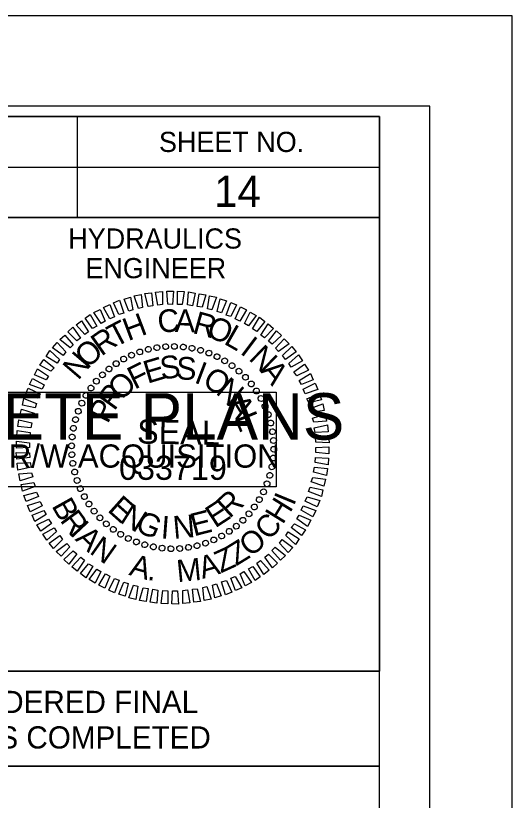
# Model space of a CAD drawing. Extents: x 1779926 to 1781626, y 618464 to 619564.
# Drawn here: x 1781502.7 to 1781626, y 619369.7 to 619564.2 of the extents above; entities that cross this region are included whole.
import ezdxf

# ---------------------------------------------------------------- set-up
doc = ezdxf.new("R2010")
doc.units = 0
for name, color, linetype in [('Old_Level_58', 7, 'Continuous'), ('Sheet Data Field CELL', 7, 'Continuous'), ('Sheet Plot Border Inside CELL', 7, 'Continuous'), ('Sheet Plot Border Outside CELL', 7, 'Continuous'), ('Sheet Professional Seal CELL', 7, 'Continuous'), ('Sheet Profile CELL', 7, 'Continuous'), ('Sheet Profile Grid Major CELL', 7, 'Continuous'), ('Sheet Profile Grid Minor CELL', 7, 'Continuous'), ('Sheet Sticker Exception Certification CELL', 7, 'Continuous'), ('Sheet Sticker Incomplete CELL', 7, 'Continuous')]:
    doc.layers.add(name, color=color, linetype=linetype)

msp = doc.modelspace()

# ---------------------------------------------------------------- linework, layer by layer
at = {"layer": 'Old_Level_58'}
msp.add_lwpolyline([(1781392.9, 619378.14), (1781592.95, 619378.14), (1781592.95, 619314.19), (1781392.9, 619314.19)], close=True, dxfattribs=at)
at = {"layer": 'Sheet Plot Border Inside CELL'}
msp.add_lwpolyline([(1779938.96, 618486.64), (1781605.46, 618486.64), (1781605.46, 619541.74), (1779938.96, 619541.74)], close=True, dxfattribs=at)
at = {"layer": 'Sheet Plot Border Outside CELL'}
msp.add_lwpolyline([(1779925.96, 618464.19), (1781625.96, 618464.19), (1781625.96, 619564.19), (1779925.96, 619564.19)], close=True, dxfattribs=at)
at = {"layer": 'Sheet Professional Seal CELL'}
for p, q in [((1781535.57, 619481.47), (1781535.57, 619481.47)), ((1781537.77, 619481.87), (1781537.77, 619481.87)), ((1781539.92, 619482.17), (1781539.92, 619482.17)), ((1781542.12, 619482.22), (1781542.12, 619482.22)), ((1781544.32, 619482.07), (1781544.32, 619482.07)), ((1781546.47, 619481.72), (1781546.47, 619481.72)), ((1781548.57, 619481.27), (1781548.57, 619481.27)), ((1781529.52, 619479.07), (1781529.52, 619479.07)), ((1781531.47, 619480.07), (1781531.47, 619480.07)), ((1781533.47, 619480.87), (1781533.47, 619480.87)), ((1781550.67, 619480.57), (1781550.67, 619480.57)), ((1781552.67, 619479.67), (1781552.67, 619479.67)), ((1781527.62, 619477.92), (1781527.62, 619477.92)), ((1781554.62, 619478.67), (1781554.62, 619478.67)), ((1781556.42, 619477.42), (1781556.42, 619477.42)), ((1781525.87, 619476.67), (1781525.87, 619476.67)), ((1781558.17, 619476.07), (1781558.17, 619476.07)), ((1781522.72, 619473.62), (1781522.72, 619473.62)), ((1781524.22, 619475.17), (1781524.22, 619475.17)), ((1781559.72, 619474.57), (1781559.72, 619474.57)), ((1781521.37, 619471.87), (1781521.37, 619471.87)), ((1781561.22, 619472.92), (1781561.22, 619472.92)), ((1781520.12, 619470.07), (1781520.12, 619470.07)), ((1781562.47, 619471.17), (1781562.47, 619471.17)), ((1781519.12, 619468.12), (1781519.12, 619468.12)), ((1781563.62, 619469.27), (1781563.62, 619469.27)), ((1781518.22, 619466.12), (1781518.22, 619466.12)), ((1781564.62, 619467.32), (1781564.62, 619467.32)), ((1781517.52, 619464.02), (1781517.52, 619464.02)), ((1781565.42, 619465.32), (1781565.42, 619465.32)), ((1781517.07, 619461.92), (1781517.07, 619461.92)), ((1781566.02, 619463.22), (1781566.02, 619463.22)), ((1781516.72, 619459.77), (1781516.72, 619459.77)), ((1781566.42, 619461.02), (1781566.42, 619461.02)), ((1781566.72, 619458.87), (1781566.72, 619458.87)), ((1781516.57, 619457.57), (1781516.57, 619457.57)), ((1781541.67, 619457.12), (1781541.67, 619457.12)), ((1781566.77, 619456.67), (1781566.77, 619456.67)), ((1781516.62, 619455.37), (1781516.62, 619455.37)), ((1781566.62, 619454.47), (1781566.62, 619454.47)), ((1781516.92, 619453.22), (1781516.92, 619453.22)), ((1781566.27, 619452.32), (1781566.27, 619452.32)), ((1781517.32, 619451.02), (1781517.32, 619451.02)), ((1781565.82, 619450.22), (1781565.82, 619450.22)), ((1781517.92, 619448.92), (1781517.92, 619448.92)), ((1781565.12, 619448.12), (1781565.12, 619448.12)), ((1781518.72, 619446.92), (1781518.72, 619446.92)), ((1781564.22, 619446.12), (1781564.22, 619446.12)), ((1781519.72, 619444.97), (1781519.72, 619444.97)), ((1781563.22, 619444.17), (1781563.22, 619444.17)), ((1781520.87, 619443.07), (1781520.87, 619443.07)), ((1781561.97, 619442.37), (1781561.97, 619442.37)), ((1781522.12, 619441.32), (1781522.12, 619441.32)), ((1781560.62, 619440.62), (1781560.62, 619440.62)), ((1781523.62, 619439.67), (1781523.62, 619439.67)), ((1781559.12, 619439.07), (1781559.12, 619439.07)), ((1781525.17, 619438.17), (1781525.17, 619438.17)), ((1781526.92, 619436.82), (1781526.92, 619436.82)), ((1781555.72, 619436.32), (1781555.72, 619436.32)), ((1781557.47, 619437.57), (1781557.47, 619437.57)), ((1781528.72, 619435.57), (1781528.72, 619435.57)), ((1781530.67, 619434.57), (1781530.67, 619434.57)), ((1781553.82, 619435.17), (1781553.82, 619435.17)), ((1781532.67, 619433.67), (1781532.67, 619433.67)), ((1781534.77, 619432.97), (1781534.77, 619432.97)), ((1781536.87, 619432.52), (1781536.87, 619432.52)), ((1781547.77, 619432.77), (1781547.77, 619432.77)), ((1781549.87, 619433.37), (1781549.87, 619433.37)), ((1781551.87, 619434.17), (1781551.87, 619434.17)), ((1781539.02, 619432.17), (1781539.02, 619432.17)), ((1781541.22, 619432.02), (1781541.22, 619432.02)), ((1781543.42, 619432.07), (1781543.42, 619432.07)), ((1781545.57, 619432.37), (1781545.57, 619432.37))]:
    msp.add_line(p, q, dxfattribs=at)
for points in [[(1781533.17, 619491.57), (1781532.12, 619494.72), (1781533.82, 619495.07), (1781534.22, 619491.82)], [(1781535.57, 619492.12), (1781534.77, 619495.32), (1781536.42, 619495.47), (1781536.77, 619492.27)], [(1781537.97, 619492.42), (1781537.42, 619495.62), (1781539.12, 619495.82), (1781539.17, 619492.57)], [(1781540.47, 619492.67), (1781540.22, 619495.92), (1781541.87, 619495.87), (1781541.67, 619492.62)], [(1781542.87, 619492.62), (1781542.87, 619495.87), (1781544.52, 619495.82), (1781544.07, 619492.57)], [(1781545.37, 619492.47), (1781545.57, 619495.72), (1781547.22, 619495.42), (1781546.57, 619492.27)], [(1781547.77, 619492.07), (1781548.22, 619495.27), (1781549.87, 619495.02), (1781548.97, 619491.92)], [(1781550.32, 619491.52), (1781550.82, 619494.77), (1781552.52, 619494.37), (1781551.37, 619491.27)], [(1781528.32, 619490.12), (1781527.02, 619493.02), (1781528.52, 619493.62), (1781529.57, 619490.42)], [(1781530.77, 619490.92), (1781529.62, 619493.92), (1781531.17, 619494.37), (1781531.82, 619491.27)], [(1781552.72, 619490.87), (1781553.47, 619493.97), (1781555.02, 619493.47), (1781553.77, 619490.52)], [(1781554.97, 619489.97), (1781556.12, 619493.12), (1781557.52, 619492.52), (1781556.12, 619489.62)], [(1781523.97, 619487.87), (1781522.12, 619490.57), (1781523.67, 619491.37), (1781524.92, 619488.47)], [(1781526.12, 619489.07), (1781524.52, 619491.87), (1781526.07, 619492.57), (1781527.22, 619489.52)], [(1781557.22, 619489.02), (1781558.47, 619491.97), (1781560.02, 619491.27), (1781558.32, 619488.47)], [(1781521.77, 619486.62), (1781519.92, 619489.17), (1781521.22, 619490.12), (1781522.87, 619487.22)], [(1781559.52, 619487.87), (1781560.87, 619490.72), (1781562.37, 619489.87), (1781560.47, 619487.27)], [(1781561.47, 619486.52), (1781563.22, 619489.42), (1781564.52, 619488.37), (1781562.57, 619485.92)], [(1781517.87, 619483.57), (1781515.67, 619485.77), (1781516.87, 619486.97), (1781518.82, 619484.27)], [(1781519.87, 619485.12), (1781517.72, 619487.52), (1781519.07, 619488.57), (1781520.82, 619485.77)], [(1781563.52, 619485.02), (1781565.37, 619487.77), (1781566.67, 619486.67), (1781564.47, 619484.32)], [(1781516.22, 619481.82), (1781513.67, 619483.87), (1781514.92, 619485.02), (1781517.02, 619482.62)], [(1781565.42, 619483.47), (1781567.47, 619486.07), (1781568.67, 619484.87), (1781566.37, 619482.72)], [(1781514.47, 619479.92), (1781511.87, 619481.87), (1781512.97, 619483.17), (1781515.17, 619480.82)], [(1781567.22, 619481.72), (1781569.37, 619484.07), (1781570.57, 619482.87), (1781567.97, 619480.92)], [(1781512.97, 619478.02), (1781510.27, 619479.72), (1781511.22, 619481.17), (1781513.62, 619478.97)], [(1781568.97, 619479.92), (1781571.27, 619482.17), (1781572.32, 619480.82), (1781569.67, 619478.92)], [(1781570.47, 619477.97), (1781572.92, 619480.07), (1781573.87, 619478.62), (1781571.07, 619477.02)], [(1781511.47, 619476.02), (1781508.67, 619477.52), (1781509.67, 619478.92), (1781512.27, 619476.92)], [(1781571.77, 619475.92), (1781574.42, 619477.82), (1781575.37, 619476.32), (1781572.47, 619474.92)], [(1781510.27, 619473.87), (1781507.42, 619475.12), (1781508.17, 619476.67), (1781510.87, 619474.82)], [(1781573.07, 619473.72), (1781575.87, 619475.47), (1781576.52, 619473.92), (1781573.67, 619472.77)], [(1781509.27, 619471.57), (1781506.17, 619472.72), (1781506.92, 619474.27), (1781509.77, 619472.67)], [(1781508.27, 619469.37), (1781505.17, 619470.27), (1781505.82, 619471.82), (1781508.82, 619470.42)], [(1781574.07, 619471.57), (1781577.02, 619473.07), (1781577.67, 619471.47), (1781574.57, 619470.47)], [(1781574.97, 619469.22), (1781578.02, 619470.52), (1781578.57, 619468.97), (1781575.47, 619468.17)], [(1781507.52, 619466.97), (1781504.42, 619467.62), (1781504.77, 619469.27), (1781507.92, 619468.02)], [(1781575.77, 619466.82), (1781578.97, 619467.97), (1781579.27, 619466.32), (1781576.12, 619465.77)], [(1781506.87, 619464.57), (1781503.77, 619464.97), (1781504.12, 619466.67), (1781507.27, 619465.62)], [(1781506.47, 619462.02), (1781503.27, 619462.32), (1781503.47, 619464.02), (1781506.72, 619463.22)], [(1781576.37, 619464.42), (1781579.52, 619465.37), (1781579.82, 619463.67), (1781576.67, 619463.37)], [(1781576.82, 619462.02), (1781580.07, 619462.72), (1781580.22, 619461.02), (1781577.02, 619460.82)], [(1781506.22, 619459.62), (1781502.97, 619459.72), (1781503.07, 619461.37), (1781506.32, 619460.82)], [(1781577.12, 619459.62), (1781580.37, 619460.02), (1781580.47, 619458.32), (1781577.22, 619458.42)], [(1781506.17, 619457.12), (1781502.92, 619456.97), (1781502.92, 619458.67), (1781506.17, 619458.32)], [(1781506.22, 619454.62), (1781502.97, 619454.22), (1781502.87, 619455.92), (1781506.12, 619455.82)], [(1781577.17, 619457.12), (1781580.42, 619457.27), (1781580.42, 619455.57), (1781577.17, 619455.92)], [(1781577.12, 619454.62), (1781580.37, 619454.52), (1781580.27, 619452.87), (1781577.02, 619453.42)], [(1781506.52, 619452.22), (1781503.27, 619451.52), (1781503.12, 619453.22), (1781506.32, 619453.42)], [(1781576.87, 619452.22), (1781580.07, 619451.92), (1781579.87, 619450.22), (1781576.62, 619451.02)], [(1781506.97, 619449.82), (1781503.82, 619448.87), (1781503.52, 619450.57), (1781506.67, 619450.87)], [(1781507.57, 619447.42), (1781504.37, 619446.27), (1781504.07, 619447.92), (1781507.22, 619448.47)], [(1781576.47, 619449.67), (1781579.57, 619449.27), (1781579.22, 619447.57), (1781576.07, 619448.62)], [(1781508.37, 619445.02), (1781505.32, 619443.72), (1781504.77, 619445.27), (1781507.87, 619446.07)], [(1781575.82, 619447.27), (1781578.92, 619446.62), (1781578.57, 619444.97), (1781575.42, 619446.22)], [(1781575.07, 619444.87), (1781578.17, 619443.97), (1781577.52, 619442.42), (1781574.52, 619443.82)], [(1781509.27, 619442.67), (1781506.32, 619441.17), (1781505.67, 619442.77), (1781508.77, 619443.77)], [(1781574.07, 619442.67), (1781577.17, 619441.52), (1781576.42, 619439.97), (1781573.57, 619441.57)], [(1781510.27, 619440.52), (1781507.47, 619438.77), (1781506.82, 619440.32), (1781509.67, 619441.47)], [(1781573.07, 619440.37), (1781575.92, 619439.12), (1781575.17, 619437.57), (1781572.47, 619439.42)], [(1781511.57, 619438.32), (1781508.92, 619436.42), (1781507.97, 619437.92), (1781510.87, 619439.32)], [(1781571.87, 619438.22), (1781574.67, 619436.72), (1781573.67, 619435.32), (1781571.07, 619437.32)], [(1781512.87, 619436.27), (1781510.42, 619434.17), (1781509.47, 619435.62), (1781512.27, 619437.22)], [(1781514.37, 619434.32), (1781512.07, 619432.07), (1781511.02, 619433.42), (1781513.67, 619435.32)], [(1781570.37, 619436.22), (1781573.07, 619434.52), (1781572.12, 619433.07), (1781569.72, 619435.27)], [(1781516.12, 619432.52), (1781513.97, 619430.17), (1781512.77, 619431.37), (1781515.37, 619433.32)], [(1781567.12, 619432.42), (1781569.67, 619430.37), (1781568.42, 619429.22), (1781566.32, 619431.62)], [(1781568.87, 619434.32), (1781571.47, 619432.37), (1781570.37, 619431.07), (1781568.17, 619433.42)], [(1781517.92, 619430.77), (1781515.87, 619428.17), (1781514.67, 619429.37), (1781516.97, 619431.52)], [(1781565.47, 619430.67), (1781567.67, 619428.47), (1781566.47, 619427.27), (1781564.52, 619429.97)], [(1781519.82, 619429.22), (1781517.97, 619426.47), (1781516.67, 619427.57), (1781518.87, 619429.92)], [(1781563.47, 619429.12), (1781565.62, 619426.72), (1781564.27, 619425.67), (1781562.52, 619428.47)], [(1781521.87, 619427.72), (1781520.12, 619424.82), (1781518.82, 619425.87), (1781520.77, 619428.32)], [(1781523.82, 619426.37), (1781522.47, 619423.52), (1781520.97, 619424.37), (1781522.87, 619426.97)], [(1781561.57, 619427.62), (1781563.42, 619425.07), (1781562.12, 619424.12), (1781560.47, 619427.02)], [(1781526.12, 619425.22), (1781524.87, 619422.27), (1781523.32, 619422.97), (1781525.02, 619425.77)], [(1781528.37, 619424.27), (1781527.22, 619421.12), (1781525.82, 619421.72), (1781527.22, 619424.62)], [(1781557.22, 619425.17), (1781558.82, 619422.37), (1781557.27, 619421.67), (1781556.12, 619424.72)], [(1781559.37, 619426.37), (1781561.22, 619423.67), (1781559.67, 619422.87), (1781558.42, 619425.77)], [(1781530.62, 619423.37), (1781529.87, 619420.27), (1781528.32, 619420.77), (1781529.57, 619423.72)], [(1781533.02, 619422.72), (1781532.52, 619419.47), (1781530.82, 619419.87), (1781531.97, 619422.97)], [(1781550.17, 619422.67), (1781551.22, 619419.52), (1781549.52, 619419.17), (1781549.12, 619422.42)], [(1781552.57, 619423.32), (1781553.72, 619420.32), (1781552.17, 619419.87), (1781551.52, 619422.97)], [(1781555.02, 619424.12), (1781556.32, 619421.22), (1781554.82, 619420.62), (1781553.77, 619423.82)], [(1781535.57, 619422.17), (1781535.12, 619418.97), (1781533.47, 619419.22), (1781534.37, 619422.32)], [(1781537.97, 619421.77), (1781537.77, 619418.52), (1781536.12, 619418.82), (1781536.77, 619421.97)], [(1781540.47, 619421.62), (1781540.47, 619418.37), (1781538.82, 619418.42), (1781539.27, 619421.67)], [(1781542.87, 619421.57), (1781543.12, 619418.32), (1781541.47, 619418.37), (1781541.67, 619421.62)], [(1781545.37, 619421.82), (1781545.92, 619418.62), (1781544.22, 619418.42), (1781544.17, 619421.67)], [(1781547.77, 619422.12), (1781548.57, 619418.92), (1781546.92, 619418.77), (1781546.57, 619421.97)]]:
    msp.add_lwpolyline(points, close=True, dxfattribs=at)
for centre, major_axis in [((1781533.51, 619480.83), (-0.234, 0.681)), ((1781535.61, 619481.46), (-0.174, 0.699)), ((1781537.75, 619481.89), (-0.113, 0.711)), ((1781539.93, 619482.14), (-0.05, 0.718)), ((1781542.11, 619482.2), (0.013, 0.72)), ((1781544.3, 619482.06), (0.075, 0.716)), ((1781546.46, 619481.74), (0.137, 0.707)), ((1781548.59, 619481.23), (0.198, 0.692)), ((1781550.66, 619480.54), (0.258, 0.672)), ((1781529.52, 619479.06), (-0.349, 0.63)), ((1781531.47, 619480.03), (-0.293, 0.658)), ((1781552.67, 619479.66), (0.316, 0.647)), ((1781554.59, 619478.62), (0.371, 0.617)), ((1781525.89, 619476.61), (-0.453, 0.56)), ((1781527.65, 619477.91), (-0.403, 0.597)), ((1781556.42, 619477.41), (0.423, 0.582)), ((1781524.25, 619475.16), (-0.5, 0.518)), ((1781558.13, 619476.05), (0.472, 0.543)), ((1781559.72, 619474.54), (0.518, 0.5)), ((1781522.75, 619473.58), (-0.543, 0.472)), ((1781561.17, 619472.9), (0.56, 0.453)), ((1781521.38, 619471.86), (-0.582, 0.423)), ((1781562.47, 619471.15), (0.597, 0.403)), ((1781520.18, 619470.04), (-0.617, 0.371)), ((1781563.61, 619469.28), (0.63, 0.349)), ((1781519.13, 619468.12), (-0.647, 0.316)), ((1781564.59, 619467.32), (0.658, 0.293)), ((1781518.26, 619466.11), (-0.672, 0.258)), ((1781565.39, 619465.29), (0.681, 0.234)), ((1781517.57, 619464.03), (-0.692, 0.198)), ((1781566.01, 619463.19), (0.699, 0.174)), ((1781517.06, 619461.91), (-0.707, 0.137)), ((1781566.45, 619461.04), (0.711, 0.113)), ((1781516.73, 619459.74), (-0.716, 0.075)), ((1781566.69, 619458.87), (0.718, 0.05)), ((1781516.6, 619457.56), (-0.72, 0.013)), ((1781516.66, 619455.37), (-0.718, -0.05)), ((1781566.75, 619456.68), (0.72, -0.013)), ((1781516.9, 619453.2), (-0.711, -0.113)), ((1781566.62, 619454.5), (0.716, -0.075)), ((1781517.34, 619451.05), (-0.699, -0.174)), ((1781566.29, 619452.34), (0.707, -0.137)), ((1781565.78, 619450.21), (0.692, -0.198)), ((1781517.96, 619448.96), (-0.681, -0.234)), ((1781565.09, 619448.13), (0.672, -0.258)), ((1781518.76, 619446.92), (-0.658, -0.293)), ((1781564.22, 619446.13), (0.647, -0.316)), ((1781519.74, 619444.96), (-0.63, -0.349)), ((1781563.17, 619444.2), (0.617, -0.371)), ((1781520.88, 619443.1), (-0.597, -0.403)), ((1781522.18, 619441.34), (-0.56, -0.453)), ((1781561.96, 619442.38), (0.582, -0.423)), ((1781523.63, 619439.7), (-0.518, -0.5)), ((1781560.6, 619440.67), (0.543, -0.472)), ((1781525.22, 619438.19), (-0.472, -0.543)), ((1781557.46, 619437.63), (0.453, -0.56)), ((1781559.1, 619439.08), (0.5, -0.518)), ((1781526.93, 619436.83), (-0.423, -0.582)), ((1781528.76, 619435.62), (-0.371, -0.617)), ((1781555.7, 619436.33), (0.403, -0.597)), ((1781530.68, 619434.58), (-0.316, -0.647)), ((1781532.69, 619433.71), (-0.258, -0.672)), ((1781551.88, 619434.21), (0.293, -0.658)), ((1781553.83, 619435.19), (0.349, -0.63)), ((1781534.76, 619433.01), (-0.198, -0.692)), ((1781536.89, 619432.5), (-0.137, -0.707)), ((1781539.05, 619432.18), (-0.075, -0.716)), ((1781541.24, 619432.04), (-0.013, -0.72)), ((1781543.42, 619432.1), (0.05, -0.718)), ((1781545.6, 619432.35), (0.113, -0.711)), ((1781547.74, 619432.79), (0.174, -0.699)), ((1781549.84, 619433.41), (0.234, -0.681))]:
    msp.add_ellipse(centre, major_axis=major_axis, ratio=0.999708, dxfattribs=at)
at = {"layer": 'Sheet Profile CELL'}
for p, q in [((1781517.96, 619539.14), (1781517.96, 619514.14)), ((1781392.91, 619526.64), (1781592.96, 619526.64))]:
    msp.add_line(p, q, dxfattribs=at)
for points in [[(1781592.96, 619539.19), (1780092.96, 619539.19), (1780092.96, 618489.19), (1781592.96, 618489.19)], [(1781392.91, 619539.19), (1781592.96, 619539.19), (1781592.96, 619514.14), (1781392.91, 619514.14)], [(1781492.96, 619514.14), (1781592.96, 619514.14), (1781592.96, 619401.64), (1781492.96, 619401.64)]]:
    msp.add_lwpolyline(points, close=True, dxfattribs=at)
at = {"layer": 'Sheet Profile Grid Major CELL'}
msp.add_lwpolyline([(1781542.96, 619314.19), (1781542.96, 619039.19), (1781592.96, 619039.19), (1781592.96, 619389.19)], dxfattribs=at)
at = {"layer": 'Sheet Sticker Exception Certification CELL'}
for p, q in [((1781392.91, 619401.64), (1781592.95, 619401.64)), ((1781392.91, 619401.64), (1781592.95, 619401.64)), ((1781592.95, 619401.63), (1781592.95, 619378.13)), ((1781592.95, 619401.63), (1781592.95, 619378.13)), ((1781592.95, 619378.14), (1781392.91, 619378.14)), ((1781592.95, 619378.14), (1781392.91, 619378.14))]:
    msp.add_line(p, q, dxfattribs=at)
at = {"layer": 'Sheet Sticker Incomplete CELL'}
msp.add_lwpolyline([(1781420.37, 619447.38), (1781420.37, 619470.88), (1781567.37, 619470.88), (1781567.37, 619447.38)], close=True, dxfattribs=at)

# ---------------------------------------------------------------- texts
at = {"layer": 'Sheet Data Field CELL'}
msp.add_text('14', height=7.75, dxfattribs=at).set_placement((1781552, 619516.8))
at = {"layer": 'Sheet Professional Seal CELL'}
for s, height, rotation, p in [('C', 5.64, 6.2199, (1781538.22, 619485.47)), ('A', 5.64, 359.0203, (1781542.17, 619485.77)), ('R', 5.64, 344.6211, (1781546.37, 619485.57)), ('T', 5.64, 27.8198, (1781527.37, 619481.82)), ('H', 5.64, 20.6195, (1781530.62, 619483.47)), ('O', 5.64, 337.4212, (1781549.72, 619484.82)), ('L', 5.64, 330.2209, (1781554.12, 619482.97)), ('R', 5.64, 35.0205, (1781523.97, 619479.62)), ('O', 5.64, 42.2217, (1781520.52, 619476.52)), ('I', 5.64, 323.0201, (1781558.17, 619480.57)), ('N', 5.64, 315.8189, (1781560.32, 619479.02)), ('N', 5.64, 49.4235, (1781518.22, 619473.62)), ('E', 5.64, 16.6111, (1781535.42, 619472.92)), ('S', 5.64, 7.2556, (1781538.87, 619473.97)), ('S', 5.64, 357.9004, (1781542.47, 619474.02)), ('F', 5.64, 25.967, (1781532.22, 619471.42)), ('I', 5.64, 339.1896, (1781546.77, 619473.32)), ('A', 5.64, 308.6172, (1781563.27, 619476.07)), ('O', 5.64, 44.6812, (1781528.92, 619468.47)), ('O', 5.64, 329.8335, (1781548.77, 619472.62)), ('N', 5.64, 320.4766, (1781552.12, 619470.62)), ('R', 5.64, 54.0397, (1781527.17, 619466.02)), ('P', 5.64, 63.3989, (1781525.57, 619462.82)), ('A', 5.64, 301.7603, (1781554.97, 619468.02)), ('L', 5.64, 292.4008, (1781556.92, 619464.57)), ('SEAL', 5.998, 359, (1781532.82, 619458.12)), ('R', 5.64, 42.4814, (1781555.77, 619439.37)), ('E', 5.64, 318.2769, (1781525.27, 619441.47)), ('E', 5.64, 33.1241, (1781552.22, 619437.02)), ('N', 5.64, 327.634, (1781528.27, 619438.77)), ('G', 5.64, 336.9902, (1781532.07, 619436.52)), ('I', 5.64, 355.7012, (1781538.62, 619434.62)), ('N', 5.64, 5.0564, (1781541.97, 619434.47)), ('E', 5.64, 14.4118, (1781546.92, 619435.07))]:
    msp.add_text(s, height=height, rotation=rotation, dxfattribs=at).set_placement(p)
at = {"layer": 'Sheet Profile CELL'}
for s, p in [('SHEET NO.', (1781538.27, 619530.4)), ('HYDRAULICS', (1781515.77, 619506.45)), ('ENGINEER', (1781520.02, 619499.1))]:
    msp.add_text(s, height=5, dxfattribs=at).set_placement(p)
at = {"layer": 'Sheet Profile Grid Minor CELL'}
msp.add_text('033719', height=5.998, dxfattribs=at).set_placement((1781528.36, 619449.11))
for s, rotation, p in [('B', 299.1529, (1781511.53, 619442.68)), ('H', 58.3478, (1781568.99, 619437.85)), ('I', 67.5926, (1781571.73, 619442.48)), ('R', 306.2797, (1781513.55, 619439.05)), ('C', 49.4751, (1781565.69, 619433.86)), ('I', 313.2061, (1781515.94, 619435.79)), ('A', 316.7266, (1781517.29, 619434.25)), ('O', 38.7706, (1781560.95, 619429.81)), ('N', 324.9124, (1781520.8, 619431.01)), ('Z', 31.6438, (1781557.41, 619427.63)), ('Z', 24.517, (1781553.63, 619425.9)), ('A', 16.3312, (1781549.07, 619424.52)), ('A', 344.2893, (1781530.64, 619425.57)), ('M', 5.6554, (1781542.9, 619423.72)), ('.', 352.4751, (1781535.25, 619424.32))]:
    msp.add_text(s, height=5.5, rotation=rotation, dxfattribs=at).set_placement(p)
at = {"layer": 'Sheet Sticker Exception Certification CELL'}
for s, p in [('DOCUMENT NOT CONSIDERED FINAL', (1781413.98, 619391.3)), ('DOCUMENT NOT CONSIDERED FINAL', (1781413.98, 619391.3)), ('UNLESS ALL SIGNATURES COMPLETED', (1781408.91, 619382.5)), ('UNLESS ALL SIGNATURES COMPLETED', (1781408.91, 619382.5))]:
    msp.add_text(s, height=5.5, dxfattribs=at).set_placement(p)
at = {"layer": 'Sheet Sticker Incomplete CELL'}
for s, height, p in [('INCOMPLETE PLANS', 11.52, (1781429.32, 619459.08)), ('DO NOT USE FOR R/W ACQUISITION', 5.76, (1781432.57, 619452.13))]:
    msp.add_text(s, height=height, dxfattribs=at).set_placement(p)

doc.saveas('drawing.dxf')
